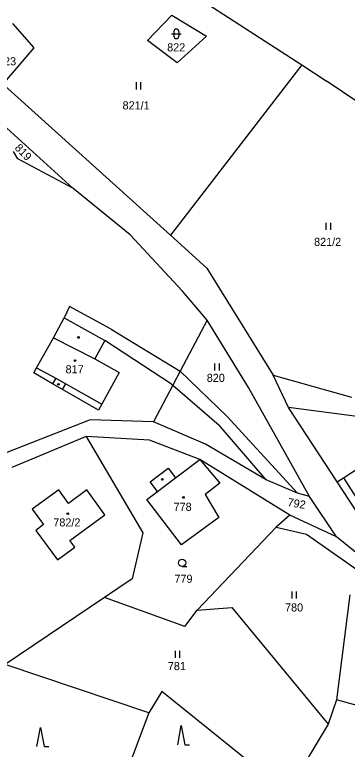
# Model space of a CAD drawing. Extents: x -670359 to -668019, y -978807 to -976674.
# Drawn here: x -669008.2 to -668938.4, y -977943.1 to -977788.7 of the extents above; entities that cross this region are included whole.
import ezdxf

# ---------------------------------------------------------------- set-up
doc = ezdxf.new("R2010")
doc.units = 0
for name, color, linetype in [('Hranice parcel', 7, 'Continuous'), ('Parcelní čísla', 7, 'Continuous'), ('Vnitřní kresba', 7, 'Continuous'), ('Značky budov', 7, 'Continuous'), ('Značky kultur', 7, 'Continuous')]:
    doc.layers.add(name, color=color, linetype=linetype)

msp = doc.modelspace()

# ---------------------------------------------------------------- linework, layer by layer
at = {"layer": 'Hranice parcel'}
for p, q in [((-669004.63, -977762.49), (-668947.9, -977799.28)), ((-668975.51, -977835.05), (-669029.85, -977786.03)), ((-668947.9, -977799.28), (-668975.51, -977835.05)), ((-668947.9, -977799.28), (-668942.78, -977802.6)), ((-668975.51, -977835.05), (-668967.82, -977841.98))]:
    msp.add_line(p, q, dxfattribs=at)
for points in [[(-668980.31, -977794.17), (-668975.17, -977788.82)], [(-668975.17, -977788.82), (-668967.89, -977793.25)], [(-669008.65, -977790.57), (-669004.18, -977795.7)], [(-668974.08, -977798.83), (-668980.31, -977794.17)], [(-668967.89, -977793.25), (-668974.08, -977798.83)], [(-669004.18, -977795.7), (-669009.97, -977802.49)], [(-668902.51, -977829.76), (-668942.78, -977802.6)], [(-668995.95, -977825.18), (-669015.27, -977807.68)], [(-669007.54, -977818.98), (-669008.42, -977817.46)], [(-668995.95, -977825.18), (-669007.54, -977818.98)], [(-668983.97, -977834.97), (-668995.95, -977825.18)], [(-668972.94, -977846.83), (-668983.97, -977834.97)], [(-668967.82, -977841.98), (-668953.94, -977864.48)], [(-668967.75, -977852.92), (-668972.94, -977846.83)], [(-669000.03, -977856.59), (-668997.78, -977852.44)], [(-668997.78, -977852.44), (-668989.3, -977857.18)], [(-668967.75, -977852.92), (-668973.43, -977863.65)], [(-668959.07, -977867.03), (-668967.75, -977852.92)], [(-669003.58, -977862.9), (-669000.03, -977856.59)], [(-668989.3, -977857.18), (-668991.4, -977861.02)], [(-668991.4, -977861.02), (-668986.28, -977863.91)], [(-669004.17, -977863.98), (-669003.58, -977862.9)], [(-668973.43, -977863.65), (-668974.97, -977866.57)], [(-669000.22, -977866.27), (-669004.17, -977863.98)], [(-668986.28, -977863.91), (-668989.91, -977870.54)], [(-668950.68, -977871.29), (-668953.94, -977864.48)], [(-668953.94, -977864.48), (-668937.48, -977869.11)], [(-668998.15, -977867.48), (-669000.22, -977866.27)], [(-668974.97, -977866.57), (-668979.05, -977874.28)], [(-668990.62, -977871.85), (-668998.15, -977867.48)], [(-668946.27, -977889.98), (-668959.07, -977867.03)], [(-668989.91, -977870.54), (-668990.62, -977871.85)], [(-668935.78, -977873.24), (-668950.68, -977871.29)], [(-668940.45, -977886.91), (-668950.68, -977871.29)], [(-668992.35, -977873.84), (-669009.83, -977880.75)], [(-668979.05, -977874.28), (-668992.35, -977873.84)], [(-668968.1, -977878.95), (-668979.05, -977874.28)], [(-668993.16, -977877.36), (-669008.8, -977883.88)], [(-668979.87, -977878.12), (-668993.16, -977877.36)], [(-668993.16, -977877.36), (-668981.26, -977897.61)], [(-668969.29, -977882.2), (-668979.87, -977878.12)], [(-668955.39, -977886.43), (-668968.1, -977878.95)], [(-668939.12, -977886.04), (-668930.5, -977880.4)], [(-668974.42, -977886.05), (-668969.29, -977882.2)], [(-668950.45, -977893.88), (-668969.29, -977882.2)], [(-668969.29, -977882.2), (-668965.14, -977887.17)], [(-668979.72, -977886.89), (-668975.94, -977884.02)], [(-668975.94, -977884.02), (-668974.42, -977886.05)], [(-668978.22, -977888.89), (-668979.72, -977886.89)], [(-668948.83, -977889.25), (-668955.39, -977886.43)], [(-668940.45, -977886.91), (-668939.12, -977886.04)], [(-668931.56, -977900.47), (-668940.45, -977886.91)], [(-668998.95, -977888.56), (-669004.5, -977892.61)], [(-668996.86, -977891.41), (-668998.95, -977888.56)], [(-668965.14, -977887.17), (-668968.2, -977889.56)], [(-668993.07, -977888.6), (-668996.86, -977891.41)], [(-668989.29, -977893.83), (-668993.07, -977888.6)], [(-668980.45, -977890.57), (-668978.22, -977888.89)], [(-668968.2, -977889.56), (-668965.33, -977894.37)], [(-668946.27, -977889.98), (-668948.83, -977889.25)], [(-668940.62, -977898.47), (-668946.27, -977889.98)], [(-668973.19, -977900.11), (-668980.45, -977890.57)], [(-669004.5, -977892.61), (-669002.16, -977895.86)], [(-668996.59, -977899.21), (-668989.29, -977893.83)], [(-668965.33, -977894.37), (-668973.19, -977900.11)], [(-668950.45, -977893.88), (-668953.26, -977896.44)], [(-668940.62, -977898.47), (-668950.45, -977893.88)], [(-669002.16, -977895.86), (-669003.78, -977897.09)], [(-669003.78, -977897.09), (-668999.21, -977903.25)], [(-668981.26, -977897.61), (-668983.55, -977907.28)], [(-668953.26, -977896.44), (-668969.9, -977913.84)], [(-668995.58, -977900.58), (-668996.59, -977899.21)], [(-668920.96, -977914.34), (-668940.62, -977898.47)], [(-668999.21, -977903.25), (-668995.58, -977900.58)], [(-668983.55, -977907.28), (-668989.35, -977911.21)], [(-668989.35, -977911.21), (-669010.16, -977925.29)], [(-668972.47, -977917.27), (-668989.35, -977911.21)], [(-668937.84, -977910.61), (-668940.59, -977932.71)], [(-668972.47, -977917.27), (-668969.9, -977913.84)], [(-668969.9, -977913.84), (-668962.61, -977913.3)], [(-668962.61, -977913.3), (-668942.34, -977937.8)], [(-668980.01, -977935.45), (-669010.16, -977925.29)], [(-668977.32, -977930.92), (-668980.01, -977935.45)], [(-668950.95, -977952.16), (-668977.32, -977930.92)], [(-668940.59, -977932.71), (-668942.34, -977937.8)], [(-668923.07, -977937.54), (-668940.59, -977932.71)], [(-668980.01, -977935.45), (-668985.45, -977949.79)], [(-668942.34, -977937.8), (-668950.95, -977952.16)]]:
    msp.add_lwpolyline(points, dxfattribs=at)
at = {"layer": 'Vnitřní kresba'}
for points in [[(-668996.65, -977850.04), (-668997.78, -977852.44)], [(-668987.93, -977854.79), (-668996.65, -977850.04)], [(-668987.93, -977854.79), (-668973.43, -977863.65)], [(-669000.03, -977856.59), (-668991.4, -977861.02)], [(-668975.24, -977866.34), (-668989.3, -977857.18)], [(-669003.58, -977862.9), (-668999.58, -977865.13)], [(-668963.58, -977873.18), (-668973.43, -977863.65)], [(-668999.58, -977865.13), (-669000.22, -977866.27)], [(-668999.58, -977865.13), (-668997.48, -977866.31)], [(-668998.15, -977867.48), (-668997.48, -977866.31)], [(-668997.48, -977866.31), (-668989.91, -977870.54)], [(-668975.24, -977866.34), (-668974.97, -977866.57)], [(-668974.97, -977866.57), (-668965.26, -977875.01)], [(-668948.83, -977889.25), (-668963.58, -977873.18)], [(-668955.39, -977886.43), (-668965.26, -977875.01)], [(-668978.22, -977888.89), (-668974.42, -977886.05)], [(-668939.12, -977886.04), (-668936.39, -977890.31)], [(-668953.26, -977896.44), (-668946.94, -977897.9)], [(-668946.94, -977897.9), (-668930.47, -977909.42)]]:
    msp.add_lwpolyline(points, dxfattribs=at)
at = {"layer": 'Značky budov'}
for centre in [(-668995.52, -977861.39), (-668972.75, -977890.17), (-668997.05, -977893.56)]:
    msp.add_circle(centre, 0.175, dxfattribs=at)
at = {"layer": 'Značky kultur'}
for p, q in [((-668975.25, -977792.73), (-668973.25, -977792.73)), ((-668974.75, -977792.23), (-668974.75, -977793.23)), ((-668973.75, -977792.23), (-668973.75, -977793.23)), ((-668982.7, -977802.91), (-668982.7, -977804.41)), ((-668981.7, -977804.41), (-668981.7, -977802.91)), ((-668942.83, -977832.45), (-668942.83, -977833.95)), ((-668941.83, -977833.95), (-668941.83, -977832.45)), ((-668966.21, -977862.01), (-668966.21, -977863.51)), ((-668965.21, -977863.51), (-668965.21, -977862.01)), ((-668973.04, -977904.66), (-668972.04, -977904.66)), ((-668950, -977909.93), (-668950, -977911.43)), ((-668949, -977911.43), (-668949, -977909.93)), ((-668974.5, -977922.39), (-668974.5, -977923.89)), ((-668973.5, -977923.89), (-668973.5, -977922.39))]:
    msp.add_line(p, q, dxfattribs=at)
for points in [[(-669003.52, -977942.48), (-669002.77, -977938.48), (-669002.02, -977942.48), (-669001.02, -977942.48)], [(-668973.97, -977942.12), (-668973.22, -977938.12), (-668972.47, -977942.12), (-668971.47, -977942.12)]]:
    msp.add_lwpolyline(points, dxfattribs=at)
for centre, radius in [((-668994.8, -977856.54), 0.175), ((-668995.52, -977861.39), 0.175), ((-668999, -977866.41), 0.175), ((-668977.18, -977886.39), 0.175), ((-668972.75, -977890.17), 0.175), ((-668997.05, -977893.56), 0.175), ((-668973.04, -977903.91), 0.75)]:
    msp.add_circle(centre, radius, dxfattribs=at)
for centre, start, end in [((-668974.25, -977792.23), 0, 180), ((-668974.25, -977793.23), 180, 0)]:
    msp.add_arc(centre, 0.5, start, end, dxfattribs=at)

# ---------------------------------------------------------------- texts
at = {"layer": 'Parcelní čísla'}
for s, p in [('822', (-668976.18, -977796.43)), ('823', (-669011.69, -977799.36)), ('821/1', (-668985.54, -977808.62)), ('821/2', (-668945.33, -977837.31)), ('817', (-668997.51, -977864.09)), ('820', (-668967.86, -977865.88)), ('778', (-668974.83, -977892.98)), ('782/2', (-669000.08, -977896.26)), ('779', (-668974.65, -977908.09)), ('780', (-668951.43, -977914.13)), ('781', (-668976.04, -977926.45))]:
    msp.add_text(s, height=1.7, dxfattribs=at).set_placement(p)
for s, rotation, p in [('819', 314.029, (-669008.31, -977816.83)), ('792', 350.3112, (-668951, -977891.95))]:
    msp.add_text(s, height=1.7, rotation=rotation, dxfattribs=at).set_placement(p)

doc.saveas('drawing.dxf')
